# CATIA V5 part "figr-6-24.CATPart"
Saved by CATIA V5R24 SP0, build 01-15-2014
Part number: Part1
Bounding box of the stored display mesh (mm): x -70 to 0, y 0 to 90, z -45 to 145
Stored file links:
  D:\KAVITA\CATIA V5-6R2014 Project_ Kavita\CATIA V5-6R2014_partfiles\Partfiles\c06_catia_v5-6r2014_prt\figr-6-24.CATPart
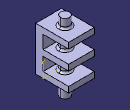
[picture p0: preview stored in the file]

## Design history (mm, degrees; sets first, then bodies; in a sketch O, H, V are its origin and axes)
Body1 (main body)
  Sketch1 on zx-plane, origin (0, 0, 0), H (-1, 0, 0), V (0, 0, 1)
    line L1 (0, 0) -> (70, 0)
    line L2 (70, 0) -> (70, 120)
    line L3 (70, 120) -> (0, 120)
    line L4 (0, 120) -> (0, 0)
    length L3 = 70
    length L2 = 120
    horizontal: L1 H, L3 H
    vertical: L2 V, L4 V
  Pad1: profile Sketch1, direction (0, 1, 0), length 20
  Sketch2 on end face of Pad1, origin (0, 20, 0), H (-1, 0, 0), V (0, 0, 1)
    projected line E1 (70, 120) -> (0, 120) from edge [face of Pad1 from Sketch1.L3 | end face of Pad1]
    point P1 (70, 120)
    line L1 (70, 120) -> (70, 104)
    line L2 (70, 104) -> (0, 104)
    line L3 (0, 104) -> (0, 120)
    point P3 (70, 120)
    length L1 = 16
    horizontal: L2 H
    vertical: L1 V, L3 V
    coincidence: P1 P3
  Sketch3 on end face of Pad1, origin (0, 20, 0), H (-1, 0, 0), V (0, 0, 1)
  Pad2: profile Sketch2, direction (0, 1, 0), length 70
  Sketch4 on end face of Pad1, origin (0, 20, 0), H (-1, 0, 0), V (0, 0, 1)
    projected line E1 (0, 0) -> (70, 0) from edge [face of Pad1 from Sketch1.L1 | end face of Pad1]
    point P1 (0, 0)
    point P3 (0, 16)
    line L1 (0, 16) -> (70, 16)
    line L2 (70, 16) -> (70, 0)
    line L3 (0, 0) -> (0, 16)
    point P5 (0, 0)
    length L2 = 16
    coincidence: P3 V, P1 P5
    horizontal: L1 H
    vertical: L2 V, L3 V
  Pad3: profile Sketch4, direction (0, 1, 0), length 70
  Sketch5 on end face of Pad1, origin (0, 20, 0), H (-1, 0, 0), V (0, 0, 1)
    point P1 (0, 68)
    line L1 (0, 68) -> (70, 68)
    line L2 (70, 68) -> (70, 52)
    line L3 (70, 52) -> (0, 52)
    line L4 (0, 52) -> (0, 68)
    coincidence: P1 V
    horizontal: L1 H, L3 H
    vertical: L2 V, L4 V
  Pad4: profile Sketch5, direction (0, 1, 0), length 70
  Sketch6 on face of Pad2, origin (0, 0, 120), H (1, 0, 0), V (0, 1, 0)
    circle A1 centre (-35, 45) radius 12.5
    radius A1 = 12.5
  Pad5: profile Sketch6, direction (0, 0, 1), length 25, opposite side length 165
  Fillet1: radius 5, on 1 edge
